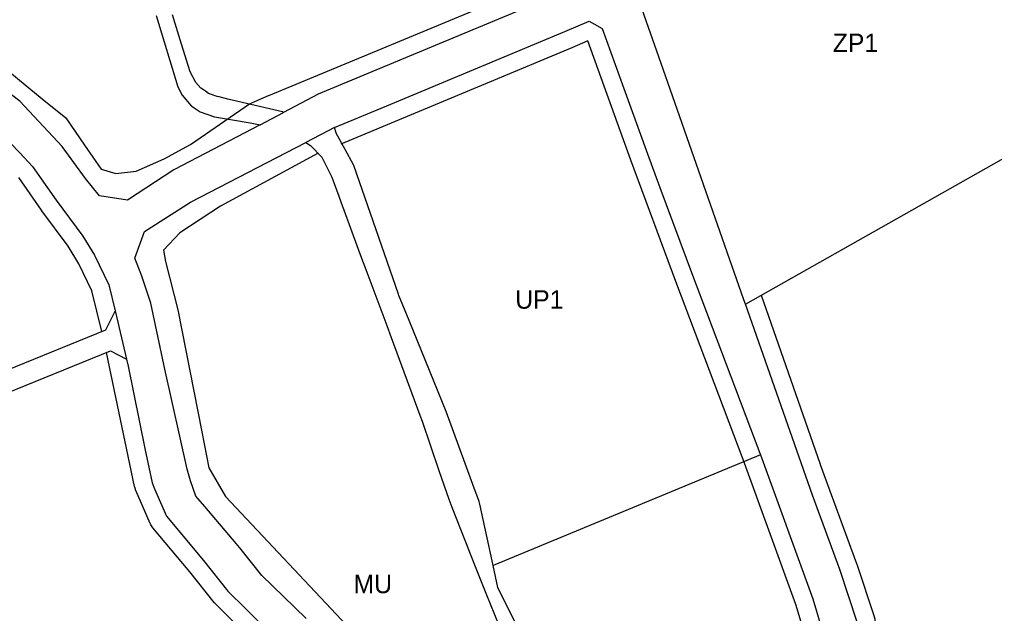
# Model space of a CAD drawing. Extents: x 7435758 to 7439981, y 5550649 to 5554049.
# Drawn here: x 7437107.4 to 7437381.1, y 5551837.1 to 5552003.8 of the extents above; entities that cross this region are included whole.
import ezdxf

# ---------------------------------------------------------------- set-up
doc = ezdxf.new("R2010")
doc.units = 0
for name, color, linetype in [('linie_rozgraniczające', 7, 'Continuous'), ('linie_zabudowy_nieprzekraczalne', 7, 'Continuous'), ('oznaczenia_przeznaczen', 7, 'Continuous')]:
    doc.layers.add(name, color=color, linetype=linetype)

msp = doc.modelspace()

# ---------------------------------------------------------------- linework, layer by layer
at = {"layer": 'linie_rozgraniczające'}
for p, q in [((7437152.86, 5551996.81), (7437150.34, 5552005.1)), ((7437247.92, 5552006.38), (7437206.29, 5551989.07)), ((7437288.06, 5551989.83), (7437282.21, 5552006.54)), ((7437145.78, 5552004.91), (7437151.85, 5551984.9)), ((7437260.48, 5552000.45), (7437267.25, 5552003.32)), ((7437267.25, 5552003.32), (7437270.95, 5552001.21)), ((7437211.61, 5551980.06), (7437260.48, 5552000.45)), ((7437270.95, 5552001.21), (7437277.04, 5551984.37)), ((7437155.26, 5551989.05), (7437152.86, 5551996.81)), ((7437156.9, 5551986.12), (7437155.26, 5551989.05)), ((7437206.29, 5551989.07), (7437191.21, 5551982.8)), ((7437310.72, 5551925.14), (7437288.06, 5551989.83)), ((7437107.51, 5551980.83), (7437098.92, 5551987.32)), ((7437158.31, 5551984.53), (7437156.9, 5551986.12)), ((7437151.85, 5551984.9), (7437153.07, 5551982.52)), ((7437159.04, 5551984.02), (7437158.31, 5551984.53)), ((7437159.56, 5551983.66), (7437159.04, 5551984.02)), ((7437160.46, 5551983.04), (7437159.56, 5551983.66)), ((7437277.04, 5551984.37), (7437283.67, 5551966.04)), ((7437311.16, 5551923.91), (7437419.08, 5551984.95)), ((7437119.37, 5551968.13), (7437107.51, 5551980.83)), ((7437153.07, 5551982.52), (7437155.6, 5551979.57)), ((7437162.92, 5551982.21), (7437160.46, 5551983.04)), ((7437163.41, 5551982.05), (7437162.92, 5551982.21)), ((7437165.88, 5551981.46), (7437163.41, 5551982.05)), ((7437179.96, 5551978.13), (7437165.88, 5551981.46)), ((7437191.21, 5551982.8), (7437181.48, 5551977.69)), ((7437155.6, 5551979.57), (7437155.79, 5551979.44)), ((7437155.79, 5551979.44), (7437156.44, 5551978.99)), ((7437156.44, 5551978.99), (7437158.12, 5551977.82)), ((7437158.12, 5551977.82), (7437162.17, 5551976.49)), ((7437174.92, 5551974.25), (7437181.48, 5551977.69)), ((7437181.21, 5551977.83), (7437179.96, 5551978.13)), ((7437181.48, 5551977.69), (7437181.21, 5551977.83)), ((7437195.83, 5551973.47), (7437211.61, 5551980.06)), ((7437162.17, 5551976.49), (7437167.19, 5551975.61)), ((7437167.19, 5551975.61), (7437172.12, 5551974.75)), ((7437174.92, 5551974.25), (7437150.73, 5551961.56)), ((7437172.12, 5551974.75), (7437174.92, 5551974.25)), ((7437195.81, 5551973.47), (7437187.73, 5551969.28)), ((7437196.25, 5551971.97), (7437195.81, 5551973.47)), ((7437195.81, 5551973.47), (7437195.83, 5551973.47)), ((7437102.2, 5551971.89), (7437107.45, 5551966.38)), ((7437196.32, 5551971.85), (7437196.25, 5551971.97)), ((7437198.8, 5551967.32), (7437196.32, 5551971.85)), ((7437125.96, 5551959.19), (7437119.37, 5551968.13)), ((7437155.38, 5551952.51), (7437187.73, 5551969.28)), ((7437187.73, 5551969.28), (7437189.1, 5551968.43)), ((7437189.1, 5551968.43), (7437192.25, 5551965.11)), ((7437201.15, 5551963.03), (7437198.8, 5551967.32)), ((7437107.45, 5551966.38), (7437111.09, 5551962.57)), ((7437192.25, 5551965.11), (7437195.02, 5551959.58)), ((7437283.67, 5551966.04), (7437287.17, 5551956.64)), ((7437111.09, 5551962.57), (7437117.68, 5551953.08)), ((7437150.73, 5551961.56), (7437137.72, 5551953.08)), ((7437201.22, 5551962.82), (7437201.15, 5551963.03)), ((7437213.75, 5551926.75), (7437201.22, 5551962.82)), ((7437129.81, 5551954.29), (7437125.96, 5551959.19)), ((7437195.02, 5551959.58), (7437196.99, 5551954.22)), ((7437287.17, 5551956.64), (7437296.34, 5551932)), ((7437117.68, 5551953.08), (7437125.18, 5551942.98)), ((7437137.72, 5551953.08), (7437129.81, 5551954.29)), ((7437196.99, 5551954.22), (7437198.07, 5551951.28)), ((7437142.48, 5551944.32), (7437155.38, 5551952.51)), ((7437198.07, 5551951.28), (7437198.12, 5551951.14)), ((7437198.12, 5551951.14), (7437202.44, 5551939.38)), ((7437125.18, 5551942.98), (7437128.43, 5551937.61)), ((7437139.79, 5551936.79), (7437142.48, 5551944.32)), ((7437202.44, 5551939.38), (7437202.54, 5551939.1)), ((7437128.43, 5551937.61), (7437132.45, 5551929.33)), ((7437141.77, 5551931.79), (7437139.79, 5551936.79)), ((7437202.54, 5551939.1), (7437205.16, 5551932.09)), ((7437144.24, 5551924.2), (7437141.77, 5551931.79)), ((7437205.16, 5551932.09), (7437210.46, 5551917.9)), ((7437296.34, 5551932), (7437315.2, 5551882.06)), ((7437132.45, 5551929.33), (7437134.25, 5551921.99)), ((7437213.89, 5551926.34), (7437213.75, 5551926.75)), ((7437216.75, 5551919.34), (7437213.89, 5551926.34)), ((7437148.18, 5551905.7), (7437144.24, 5551924.2)), ((7437311.16, 5551923.91), (7437310.72, 5551925.14)), ((7437330, 5551870.35), (7437311.16, 5551923.91)), ((7437134.25, 5551921.99), (7437131.52, 5551916.61)), ((7437134.25, 5551921.99), (7437137.41, 5551908.47)), ((7437210.46, 5551917.9), (7437211.71, 5551914.57)), ((7437227.16, 5551893.83), (7437216.75, 5551919.34)), ((7437131.52, 5551916.61), (7437060.3, 5551887.61)), ((7437211.71, 5551914.57), (7437219.76, 5551892.77)), ((7437033.37, 5551870.27), (7437132.96, 5551910.8)), ((7437132.96, 5551910.8), (7437137.41, 5551908.47)), ((7437137.41, 5551908.47), (7437137.86, 5551906.52)), ((7437137.86, 5551906.52), (7437142.62, 5551883.4)), ((7437154.48, 5551877.64), (7437148.18, 5551905.7)), ((7437234.67, 5551873.33), (7437227.16, 5551893.83)), ((7437219.76, 5551892.77), (7437220.38, 5551891.08)), ((7437220.38, 5551891.08), (7437225.13, 5551877.21)), ((7437142.62, 5551883.4), (7437144.61, 5551873.76)), ((7437315.2, 5551882.06), (7437315.34, 5551881.67)), ((7437315.34, 5551881.67), (7437240.79, 5551850.74)), ((7437315.34, 5551881.67), (7437330.07, 5551841.21)), ((7437155.41, 5551874.29), (7437154.48, 5551877.64)), ((7437225.13, 5551877.21), (7437227.86, 5551869.21)), ((7437144.61, 5551873.76), (7437145.3, 5551872.11)), ((7437156.88, 5551870), (7437155.41, 5551874.29)), ((7437145.3, 5551872.11), (7437148.67, 5551864.39)), ((7437236.41, 5551868.57), (7437234.67, 5551873.33)), ((7437159.42, 5551867.15), (7437156.88, 5551870)), ((7437227.86, 5551869.21), (7437228.74, 5551866.96)), ((7437236.58, 5551867.8), (7437236.41, 5551868.57)), ((7437337.64, 5551849.43), (7437330, 5551870.35)), ((7437169.21, 5551855.54), (7437159.42, 5551867.15)), ((7437228.74, 5551866.96), (7437233.59, 5551854.63)), ((7437239.55, 5551854.01), (7437236.58, 5551867.8)), ((7437148.67, 5551864.39), (7437159.03, 5551851.97)), ((7437175.45, 5551847.79), (7437169.21, 5551855.54)), ((7437233.59, 5551854.63), (7437233.69, 5551854.36)), ((7437159.03, 5551851.97), (7437165.9, 5551843.34)), ((7437233.69, 5551854.36), (7437233.71, 5551854.32)), ((7437233.71, 5551854.32), (7437235.65, 5551849.39)), ((7437240.3, 5551850.54), (7437239.55, 5551854.01)), ((7437235.65, 5551849.39), (7437238.33, 5551842.82)), ((7437240.79, 5551850.74), (7437240.3, 5551850.54)), ((7437241.63, 5551844.38), (7437240.3, 5551850.54)), ((7437342.53, 5551834.72), (7437337.64, 5551849.43)), ((7437181.49, 5551841.92), (7437175.45, 5551847.79)), ((7437248.93, 5551829.73), (7437241.63, 5551844.38)), ((7437165.9, 5551843.34), (7437170.79, 5551838.52)), ((7437187.89, 5551835.71), (7437181.49, 5551841.92)), ((7437238.33, 5551842.82), (7437244.76, 5551827.03)), ((7437330.07, 5551841.21), (7437333.2, 5551830.73)), ((7437170.79, 5551838.52), (7437192.04, 5551817.35))]:
    msp.add_line(p, q, dxfattribs=at)
at = {"layer": 'linie_zabudowy_nieprzekraczalne'}
for points in [[(7437099.78, 5551992.9), (7437113.79, 5551981.52), (7437120.4, 5551976.14), (7437125.63, 5551968.56), (7437130.33, 5551961.75), (7437134.43, 5551960.53), (7437140.14, 5551961.23), (7437147.97, 5551964.67), (7437155.36, 5551968.73), (7437171.99, 5551980.14), (7437177.31, 5551982.44), (7437177.37, 5551982.46), (7437245.97, 5552010.98)], [(7437327.25, 5551677.18), (7437328.56, 5551675.97), (7437328.36, 5551687.67), (7437328.36, 5551687.78), (7437328.66, 5551749.73), (7437328.02, 5551782.17), (7437328.02, 5551782.39), (7437328.03, 5551782.45), (7437329.33, 5551819.31), (7437328.28, 5551829.75), (7437325.32, 5551839.64), (7437310.51, 5551880.32), (7437291.66, 5551930.23), (7437291.66, 5551930.26), (7437278.98, 5551964.3), (7437278.97, 5551964.34), (7437266.89, 5551997.74), (7437262.43, 5551995.85), (7437262.4, 5551995.84), (7437197.61, 5551968.8)], [(7437191.25, 5551966.29), (7437163.85, 5551951.36), (7437152.38, 5551943.89), (7437147.78, 5551939.1), (7437148.4, 5551935.88), (7437151.79, 5551922.29), (7437158.55, 5551888.1), (7437160.55, 5551877.97), (7437165.17, 5551869.95), (7437199.31, 5551833.78)], [(7437130.53, 5551916.2), (7437127.72, 5551927.62), (7437124.03, 5551935.22), (7437121.03, 5551940.19), (7437113.66, 5551950.1), (7437113.64, 5551950.14), (7437113.57, 5551950.23), (7437107.2, 5551959.4)], [(7437315.57, 5551926.41), (7437332.15, 5551879.01), (7437332.17, 5551878.96), (7437342.33, 5551851.14), (7437342.38, 5551851), (7437347.27, 5551836.29), (7437347.3, 5551836.21), (7437347.39, 5551835.89), (7437347.45, 5551835.57), (7437347.49, 5551835.3), (7437349.21, 5551820.69), (7437349.22, 5551820.63), (7437349.24, 5551820.31), (7437349.25, 5551819.98), (7437349.24, 5551819.9), (7437348.7, 5551806.67), (7437348.29, 5551796.91), (7437349.28, 5551796.1), (7437363.06, 5551795.73), (7437390.83, 5551795.28)], [(7437167.28, 5551834.96), (7437162.39, 5551839.78), (7437162.28, 5551839.9), (7437162.06, 5551840.14), (7437161.99, 5551840.23), (7437155.16, 5551848.81), (7437144.83, 5551861.18), (7437144.63, 5551861.44), (7437144.45, 5551861.71), (7437144.28, 5551862), (7437144.13, 5551862.29), (7437144.09, 5551862.39), (7437140.72, 5551870.11), (7437140.7, 5551870.17), (7437140, 5551871.82), (7437139.95, 5551871.96), (7437139.84, 5551872.27), (7437139.75, 5551872.58), (7437139.71, 5551872.75), (7437131.85, 5551910.35)]]:
    msp.add_lwpolyline(points, dxfattribs=at)

# ---------------------------------------------------------------- texts
at = {"layer": 'oznaczenia_przeznaczen'}
for s, p in [('ZP1', (7437335.65, 5551994.61)), ('UP1', (7437246.54, 5551922.63)), ('MU', (7437201.15, 5551842.81))]:
    msp.add_text(s, height=5.2, dxfattribs=at).set_placement(p)

doc.saveas('drawing.dxf')
